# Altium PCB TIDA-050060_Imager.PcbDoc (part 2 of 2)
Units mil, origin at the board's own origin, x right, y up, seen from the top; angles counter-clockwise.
Board outline 989.05 x 988.04 mil, 6 copper layers (TOP, GND1, POWER1, INNER1, GND2, BOTTOM), stack 61.2 mil thick; 79 components, 47 nets, 342 pads, 154 vias.
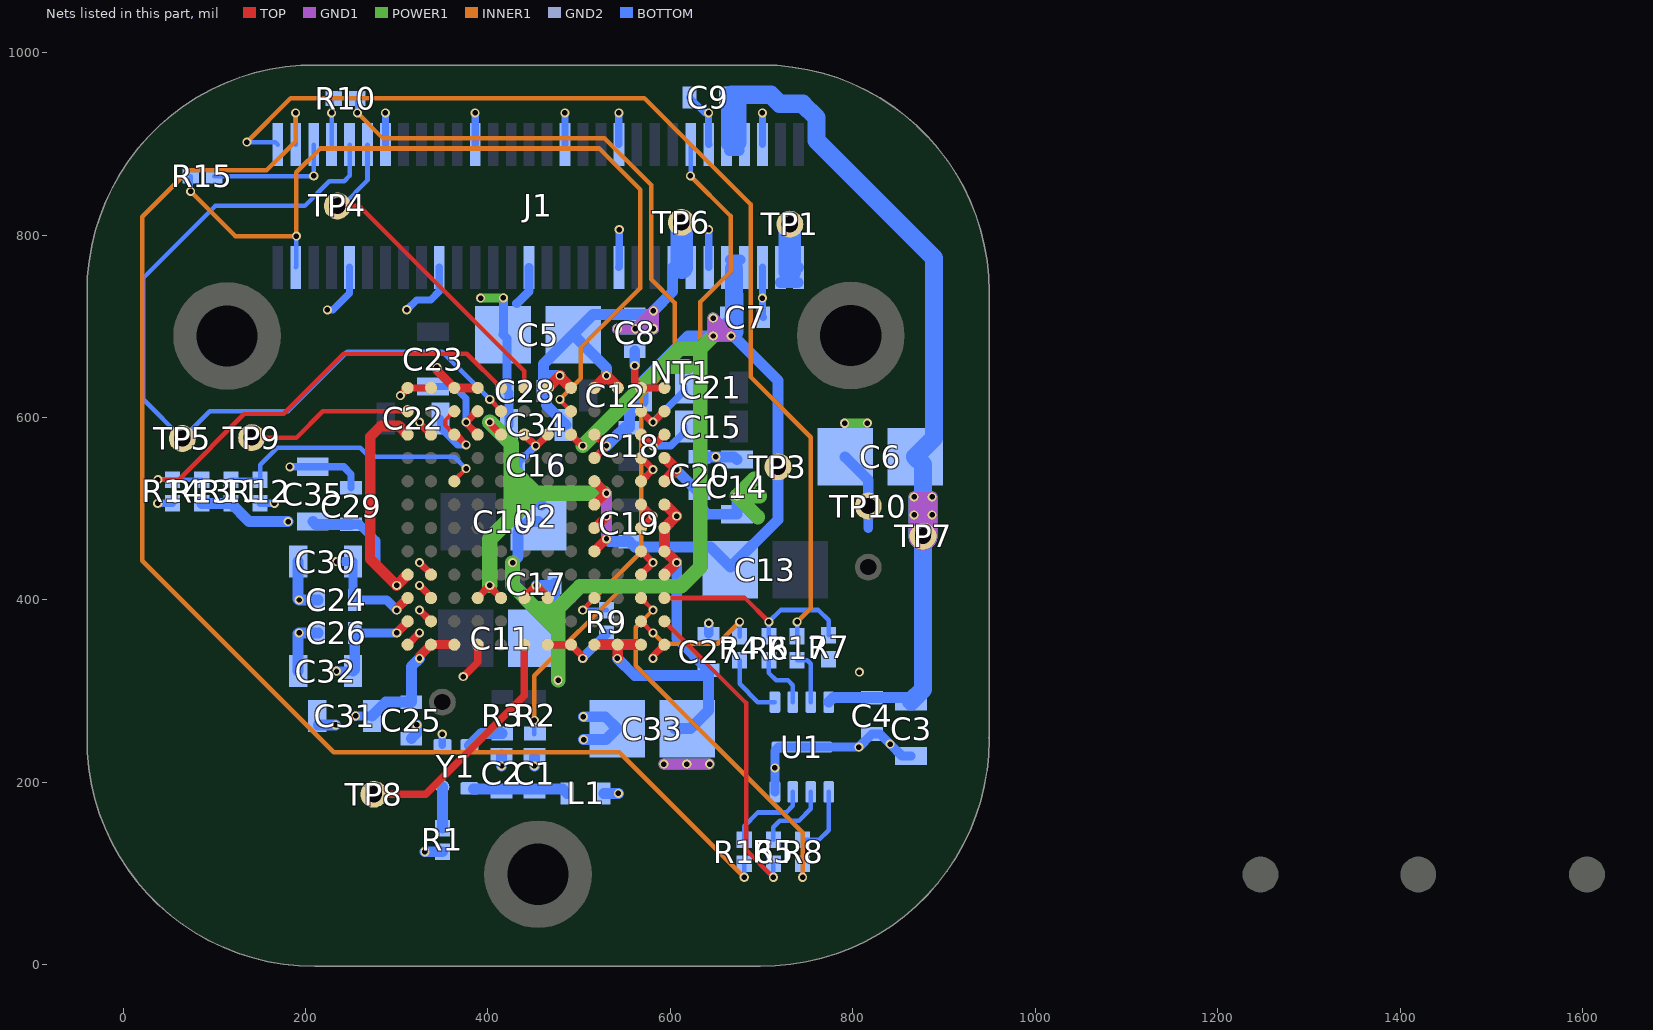
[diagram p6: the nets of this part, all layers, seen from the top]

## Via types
v1: diameter 10, hole 6, TOP to BOTTOM, tented both sides, 154 vias

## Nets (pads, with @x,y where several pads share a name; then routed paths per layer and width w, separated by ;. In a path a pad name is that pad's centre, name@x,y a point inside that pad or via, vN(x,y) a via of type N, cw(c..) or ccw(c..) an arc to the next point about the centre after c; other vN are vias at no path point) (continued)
DGND: C1.2 C2.2 C3.2 C4.2 C5.2 C6.2 C7.2 C8.2 C9.2 C14.2 C20.2 C24.2 C25.2 C26.2 C27.2 C28.2 C29.2 C30.2 C31.2 C32.2 C33.2 C34.2 C35.2 J1.5 J1.6 J1.11 J1.12 J1.21 J1.22 J1.27 J1.32 J1.37 J1.42 J1.47 J1.52 NT1.1 R7.1 R9.1 R12.1 R14.1 TP10.1 U1.4 U1.9 U2.A1 U2.A2 U2.A11 U2.A12 U2.C2 U2.D11 U2.E11 U2.F11 U2.G11 U2.H11 U2.J2 U2.J11 U2.K2 U2.L2 U2.M1 U2.M4 U2.M7 U2.M8 U2.M12 Y1.2 | length 1950.7
  TOP w8: v1(304,624) 312.01,632.01 U2.A1@312.01,632.51 U2.A2@337.6,632.51 ; U2.M1@312.01,351.02 v1(325,364) ; v1(325,389) 337.39,376.61 U2.L2@337.6,376.61 ; v1(325,416) 337.6,403.4 U2.K2@337.6,402.2 ; v1(325,441) 337.6,428.4 U2.J2@337.6,427.79 ; v1(325,595) 325,593.93 U2.C2@337.6,581.33 ; v1(373,316) 388.78,331.78 U2.M4@388.78,351.02 ; U2.M7@465.55,351.02 U2.M8@491.14,351.02 504,338.16 v1(504,336) ; v1(561,657) 561,639.42 U2.A11@567.91,632.51 U2.A12@593.5,632.51 ; U2.J11@567.91,427.79 567.91,427.91 v1(581,441) 568.62,453.38 U2.H11@567.91,453.38 ; U2.G11@567.91,478.97 580.95,492 v1(581,492) 568.44,504.56 U2.F11@567.91,504.56 ; U2.E11@567.91,530.15 568.15,530.15 v1(581,543) 568.26,555.74 U2.D11@567.91,555.74 ; v1(581,336) 581,338.51 U2.M12@593.5,351.02
  POWER1 w10: v1(392,731) v1@416.71,731 ; v1(791,593.71) v1@815.71,593.71
  INNER1 w10: v1@416.71,731 v1(417,731.29)
  BOTTOM w8: v1(38,506) R14.1@54.25,506 ; R12.1@150.25,506.02 v1(166,506) ; v1(183,546) C35.2@208,546 242,546 250,538 C29.2@250,523 ; v1(224,718) 230,718 248.31,736.31 J1.52@248.31,764.68 ; v1(287.61,934) 287.68,933.94 J1.47@287.68,899.32 ; v1(311,718.14) 321.86,729 337.18,729 346.73,738.56 J1.42@346.73,764.68 ; v1(350,253) 350,240.86 Y1.2@350.24,240.62 ; v1(386.04,934) 386.1,933.94 J1.37@386.1,899.32 ; v1(484.46,934) 484.53,933.94 J1.27@484.53,899.32 ; v1(543.52,934) 543.58,933.94 J1.21@543.58,899.32 ; J1.22@543.58,764.68 544,765.09 v1(544,806) ; C9.2@621,951 638,934 v1(641.94,934) 641.94,899.39 J1.11@642.01,899.32 ; J1.12@642.01,764.68 v1(642,806) ; v1(701,934) 701.06,933.94 J1.5@701.06,899.32 ; J1.6@701.06,764.68 701,764.61 v1(701,731) 701,711 C7.2@702,710
  BOTTOM w10: v1(417,731.29) 417,691.39 C5.2@416.61,691 421,686.61 C28.2@421,629 423,627 C34.2@423,592 ; 431.6,725 445.16,738.56 J1.32@445.16,764.68 ; v1(504,336) 504,337.01 R9.1@530,363.01 ; C27.2@642,363 642.06,363.06 v1(642.06,374.57) ; U1.4@714.63,189.57 v1(714.63,216) 714.63,234.63 718.79,238.79 U1.9@744.16,238.79 v1(806.79,238.79) C4.2@821,253 830,253 v1(841,242) 854,229 C3.2@864,229 ; 817,478.66 TP10.1@817,503
  BOTTOM w12: C32.2@192,322 192,363 v1(193,364) C26.2@214,364 ; C30.2@192,442 192,401 v1(193,400) C24.2@214,400 ; C31.2@214,263 v1(233,263) ; C25.2@316,248 322,254 v1(322,263) ; v1(415,218) C2.2@415,230 ; v1(451,218) C1.2@451,228.5 ; v1(504.71,272) 528.61,272 C33.2@541.61,259 529.61,247 v1(505,247) ; v1(561,657) C8.2@561,673 ; C20.2@632,557 670,557 C14.2@673,554 ; C6.2@791.61,557 817,531.61 TP10.1@817,503
  other v1: 807.22,321 650,557 816,594
EXT_CLK: J1.13 R2.1 | length 790.1
  INNER1 w5: v1(451,268) 451,317 551,417 613,417 633,437 633,727 666,760 666,821 v1(622,865)
  BOTTOM w5: R2.1@451,253 v1(451,268) ; v1(622,865) 622.32,865.32 J1.13@622.32,899.32
GPIO0: J1.53 R10.2 | length 51.7
  BOTTOM w5: J1.53@228.62,899.32 228.62,933.94 v1(228.56,934) 228.56,947.55 R10.2@231.01,950
GPIO1: J1.55 R15.1 | length 143.4
  BOTTOM w5: R15.1@99.99,864.7 208.58,864.7 208.94,865.06 J1.55@208.94,899.32
  other v1: 209,865
GPIO2: J1.57 R16.1 | length 1464.1
  INNER1 w5: v1(189.19,934) 189.19,902.94 157.25,871 72,871 21,820 21,443 231,233 544,233 v1(681,96)
  BOTTOM w5: v1(189.19,934) 189.25,933.94 J1.57@189.25,899.32 ; v1(681,96) R16.1@681,111.02
GPIO3: J1.59 R17.1 | length 1162.8
  INNER1 w5: v1(135.72,902) 184.03,950.31 571.34,950.31 688,833.65 688,644.5 754,578.5 754,391 v1(739,376)
  BOTTOM w5: v1(135.72,902) 166.89,902 J1.59@169.57,899.32 ; R17.1@739,360 v1(739,376)
HOLD: R17.2 U1.7 | length 58.7
  BOTTOM w5: R17.2@739,334.02 749.98,334.02 754,330 U1.7@754,288
I2C_SCL: J1.49 TP4.1 U2.A6 | length 394.4
  TOP w5: TP4.1@229,832 TP4.1@235,832 259,832 439.96,651.04 U2.A6@439.96,632.51
  BOTTOM w5: TP4.1@229,832 TP4.1@235,832 240,832 267.99,859.99 J1.49@267.99,899.32
I2C_SDA: J1.51 TP5.1 U2.B5 | length 916.9
  TOP w5: v1(402,620) 414.37,607.63 U2.B5@414.37,606.92
  BOTTOM w5: J1.51@248.31,899.32 248.31,865.01 242.3,859 226,859 199,832 101,832 22,753 22,620 TP5.1@65,577 95,607 180.87,607 245.87,672 350,672 v1(402,620)
NetC1_1: C1.1 C2.1 L1.2 Y1.4 | length 104.9
  BOTTOM w12: Y1.4@384.14,193 415,193 451,193 482,193 L1.2@487,188
NetC15_1: C15.1 U2.C11 U2.C12 | length 82.4
  TOP w5: v1@580.24,569 v1(581,569) v1@581.17,569
  TOP w8: U2.C11@567.91,581.33 v1@580.24,569 ; v1@581.17,569 U2.C12@593.5,581.33
  BOTTOM w8: v1(581,569) 600.61,569 615,583.39 C15.1@615,590
NetC21_1: C21.1 U2.B11 U2.B12 | length 87.5
  TOP w5: v1@579.83,595 v1(581,595) v1@581.58,595
  TOP w8: U2.B11@567.91,606.92 v1@579.83,595 ; v1@581.58,595 U2.B12@593.5,606.92
  BOTTOM w8: v1(581,595) 615,629 C21.1@615,633
NetC22_1: C22.1 U2.B3 U2.C3 | length 97.4
  TOP w5: U2.C3@363.19,581.33 353,591.52 353,596.73 U2.B3@363.19,606.92
  TOP w8: U2.C3@363.19,581.33 364.67,581.33 v1(376,570)
  BOTTOM w8: C22.1@348,599 348,589 367,570 v1(376,570)
NetC23_1: C23.1 U2.B4 U2.C4 | length 104.1
  TOP w8: U2.C4@388.78,581.33 376,594.11 v1(376,595) 387.92,606.92 U2.B4@388.78,606.92
  BOTTOM w8: C23.1@340,634 363,634 376,621 v1(376,595)
NetR1_1: R1.1 Y1.1 | length 45.1
  BOTTOM w12: R1.1@350,149.99 350.24,150.23 Y1.1@350.24,194.95
NetR3_1: R3.1 Y1.3 | length 41.3
  BOTTOM w12: Y1.3@379.76,240.62 392.78,253.64 R3.1@415.71,253.64
NetR4_2: R4.2 U2.L11 | length 144.9
  TOP w5: U2.L11@567.91,376.61 581,363.52 v1(581,364)
  INNER1 w5: v1(581,364) 593,352 652,352 v1(676,376)
  BOTTOM w5: R4.2@676,360 v1(676,376)
NetR5_2: R5.2 U2.L12 | length 345.1
  TOP w5: U2.L12@593.5,376.61 683,287.11 683,126 v1(713,96)
  BOTTOM w5: v1(713,96) R5.2@713,111.02
NetR6_2: R6.2 R7.2 U2.K12 | length 233.4
  TOP w5: U2.K12@593.5,402.2 681.8,402.2 v1(708,376)
  BOTTOM w5: R6.2@708,360 v1(708,376) 721,389 762.27,389 773.5,377.76 R7.2@773.5,361.23
NetR8_1: R8.1 U2.K11 | length 410.3
  TOP w5: U2.K11@567.91,402.2 567.91,402.09 v1(581,389)
  INNER1 w5: v1(581,389) 562,370 562,328 745,145 v1(745,96)
  BOTTOM w5: v1(745,96) R8.1@745,111.02
NetR9_2: R9.2 R10.1 U2.K9 | length 933.8
  TOP w5: v1(504,389) 504,389.46 U2.K9@516.73,402.2
  INNER1 w5: v1(257,934) 285,906 528,906 579,855 579,751.66 605,725.66 605,660.5 568,623.5 568,453 v1(504,389)
  BOTTOM w5: v1(257,934) R10.1@256.99,950 ; v1(504,389) R9.2@530,388.99
NetTP8_1: TP8.1 U2.M6 | length 265.7
  TOP w8: TP8.1@275,187 332,187 439.96,294.96 U2.M6@439.96,351.02
NetTP9_1: TP9.1 U2.B1 | length 183
  TOP w5: TP9.1@141,578 190.08,578 219,606.92 U2.B1@312.01,606.92
SCK: R6.1 U1.6 | length 64.5
  BOTTOM w5: R6.1@708,334.02 708,320 716,312 729,312 734.32,306.68 U1.6@734.32,288
SDI: R4.1 U1.5 | length 72.9
  BOTTOM w5: R4.1@676,334.02 676,308 696,288 U1.5@714.63,288
SDO: R5.1 U1.2 | length 81.9
  BOTTOM w5: R5.1@713,137 713,151 720,158 741,158 754,171 U1.2@754,189.57
SEL0: R11.1 R12.2 U2.E3 | length 310.5
  TOP w5: U2.E3@363.19,530.15 363.19,531.19 v1(376,544)
  BOTTOM w5: R11.1@118.25,532 R12.2@150.25,532 150.25,548.25 169,567 260,567 270.04,556.96 363.04,556.96 v1(376,544)
SEL1: R13.1 R14.2 U2.A5 | length 496.8
  TOP w5: v1(38.25,532) 61,532 133,604 176,604 242,670 376.88,670 U2.A5@414.37,632.51
  BOTTOM w5: v1(38.25,532) 54.24,532 R13.1@86.25,531.98
VAA_3V3: C7.1 C10.1 C11.1 C12.1 C13.1 C16.1 C17.1 C18.1 C19.1 J1.8 J1.10 TP3.1 U2.C5 U2.C6 U2.C7 U2.C8 U2.C9 U2.D9 U2.E9 U2.F9 U2.G9 U2.H9 U2.K4 U2.K5 U2.K6 U2.K7 | length 2744.4
  TOP w8: U2.K4@388.78,402.2 388.78,402.78 v1(402,416) 402,414.57 U2.K5@414.37,402.2 ; v1(402,595) 402,593.7 U2.C5@414.37,581.33 ; U2.K6@439.96,402.2 439.96,402.96 v1(453,416) 465.55,403.45 U2.K7@465.55,402.2 ; U2.C6@439.96,581.33 v1(452.29,569) 453.22,569 U2.C7@465.55,581.33 ; U2.C8@491.14,581.33 v1@503.47,569 ; U2.H9@516.73,453.38 U2.H9@516.73,453.73 ; U2.G9@516.73,478.97 U2.G9@516.97,478.97 ; U2.E9@516.73,530.15 U2.E9@516.85,530.15 ; U2.D9@516.73,555.74 v1(530,569) 517.67,581.33 U2.C9@516.73,581.33
  TOP w10: U2.H9@516.73,453.73 v1(530,467) ; U2.F9@516.73,504.56 529.17,517 v1(530,517) U2.E9@516.85,530.15 ; U2.G9@516.97,478.97 v1(530,492)
  GND1 w12: v1(530,467) v1(530,492) v1(530,517) ; v1(647,689.44) v1(666.69,689.44) v1(647,709.13) v1(647,689.44)
  POWER1 w16: v1(427,441) 427,416 452,391 ; 427,543 452,518 ; 433,517 452,517 ; 476,367 452,391 ; v1(477,312) 477,391 ; v1(504,569) 610.44,675.44 633,675.44 ; 593.73,656 618.73,656 ; v1(647,689.44) 633,675.44 ; 452,391 477,391 ; 477,391 501,415 612,415 633,436 633,675.44
  POWER1 w17: v1(402,416) 402,467 452,517 ; v1(402,595) 425.44,571.56 425.44,494 ; 458,517 v1@527,517
  GND2 w12: v1(530,467) v1(530,492) v1(530,517) ; v1(647,689.44) v1(666.69,689.44) v1(647,709.13) v1(647,689.44)
  BOTTOM w8: C16.1@433,548 433,549.71 v1(452.29,569)
  BOTTOM w10: C10.1@433,474 C16.1@433,548
  BOTTOM w12: v1(427,441) 433,447 433,474 445,486 C10.1@455.39,486 ; 434,529.36 C10.1@459,504.36 ; v1(453,416) 471,416 C17.1@473,418 473,380.61 477,376.61 v1(477,312) ; v1(530,467) 533,464 C19.1@555,464 561,458 644,458 666,436 718,488 TP3.1@718,546 718,640.45 v1@669.78,688.67 ; v1(530,569) 550,589 C18.1@555,589 555,602 570,617 C12.1@570,624 570,640 619.44,689.44 v1(647,689.44) C7.1@662,704.44 ; J1.10@666,773 J1.8@676.38,773 ; 669.78,763.46 671,764.68
  BOTTOM w20: 669.78,763.46 669.95,710.03 670,694
VDD_1V1: C5.1 C8.1 C14.1 C20.1 C24.1 C25.1 C26.1 C27.1 C28.1 C30.1 C31.1 C32.1 C33.1 C34.1 J1.14 J1.16 TP6.1 U2.A3 U2.A4 U2.A7 U2.A8 U2.A9 U2.A10 U2.D12 U2.E12 U2.F12 U2.G12 U2.H12 U2.J12 U2.K1 U2.L1 U2.M2 U2.M3 U2.M9 U2.M10 U2.M11 | length 1978.8
  TOP w5: U2.D12@593.5,555.74 U2.D12@594.26,555.74 ; v1@606.36,543 v1(607,543)
  TOP w8: v1(300,389) v1@300,390.19 ; U2.L1@312.01,376.01 U2.L1@312.01,376.61 ; U2.A7@465.55,632.51 U2.A7@466.49,632.51 ; v1@479,644.65 v1(479,646) ; U2.A8@491.14,632.14 U2.A8@491.14,632.51 ; v1(542,336) v1@542.32,336.32 ; U2.A10@542.32,632.51 U2.A10@542.32,633.46 ; U2.J12@593.5,427.79 U2.J12@593.79,427.79 ; U2.H12@593.5,453.38 U2.H12@594.62,453.38 ; U2.F12@593.5,504.56 U2.F12@594.44,504.56 ; v1@606.54,492 v1(607,492)
  TOP w10: v1(300,364) U2.L1@312.01,376.01 ; v1@300,390.19 U2.K1@312.01,402.2 ; v1(325,336) 325,338.42 U2.M2@337.6,351.02 U2.M3@363.19,351.02 ; v1(344,655) 344,651.7 U2.A3@363.19,632.51 U2.A4@388.78,632.51
  TOP w12: U2.A7@465.55,632.55 v1(479,646) ; v1@479,644.65 U2.A8@491.14,632.51 ; U2.M9@516.73,351.02 U2.M10@542.32,351.02 ; U2.A9@516.73,632.51 530,645.78 U2.A10@542.32,633.46 ; v1@542.32,336.32 U2.M10@542.32,351.02 ; U2.M11@567.91,351.02 U2.M10@542.32,351.02 ; U2.H12@593.5,453.38 U2.G12@593.5,478.97 v1@606.54,492 ; U2.E12@593.5,530.15 v1@606.36,543 ; U2.J12@593.79,427.79 v1(607,441) U2.H12@594.62,453.38 ; U2.D12@594.26,555.74 v1(607,543) ; U2.F12@594.44,504.56 v1(607,492)
  GND1 w12: v1(542,697.31) v1(561.69,697.31) ; v1(593,220) v1(618,220) v1@642.42,220 ; v1(561.69,697.31) v1(581.37,697.31) v1(581.37,717) v1(561.69,697.31)
  POWER1 w16: 692,533 v1(673,514) ; 696,491 v1(673,514) ; 698,514 v1(673,514)
  GND2 w12: v1(542,697.31) v1(561.69,697.31) ; v1(593,220) v1(618,220) v1@642.42,220 ; v1(561.69,697.31) v1(581.37,697.31) v1(581.37,717) v1(561.69,697.31)
  BOTTOM w10: v1(234,322) C32.1@252,322 ; v1(234,442) C30.1@252,442 252,402 C24.1@254,400 289,400 v1(300,389) ; C26.1@254,364 v1(300,364) ; v1(255,273) C31.1@273,273
  BOTTOM w12: C32.1@252,322 254,324 C26.1@254,364 ; C31.1@273,273 288,288 C25.1@316,288 316,327 v1(325,336) ; v1(479,646) 461,646 ; C34.1@483,592 485.79,592 464,613.79 464,626 C28.1@461,629 461,646 ; v1(530,646) 530,654.39 C5.1@493.39,691 ; v1(542,336) 561,317 636,317 C27.1@642,323 ; C33.1@604.61,259 C33.1@618.39,259 622,259 642,279 C27.1@642,323 ; v1(607,441) 607,358 C27.1@642,323 ; v1(607,543) 607,542 C20.1@632,517 632,503 641,494 C14.1@673,494 v1(673,514) ; 612.48,764.68 J1.16@602.64,764.68 602.64,738.27 v1(581.37,717) 577.37,713 C8.1@561,713 515.39,713 C5.1@493.39,691 ; TP6.1@612.48,812.48 TP6.1@614,814 ; 461,646 461,658.61 C5.1@493.39,691
  BOTTOM w25: 612.48,764.68 TP6.1@612.48,812.48
  other v1: 643,220
VDD_1V8: C3.1 C4.1 C6.1 C9.1 C29.1 C35.1 J1.7 J1.9 L1.1 R1.2 R11.2 R13.2 TP7.1 U1.8 U2.C1 U2.J1 | length 1776.4
  TOP w8: U2.J1@311.79,427.79 U2.J1@312.01,427.79
  TOP w12: U2.J1@311.79,427.79 v1(300,416) 271,445 271,579 283,591 302.34,591 U2.C1@312.01,581.33
  GND1 w12: v1(867.31,513) v1(887,513) v1(887,493.31) ; v1(867.31,513) v1(867.31,493.31) v1(887,493.31) ; v1(867.31,513) v1(887,493.31)
  GND1 w32: TP7.1@877,470 877,492
  GND2 w12: v1(867.31,493.31) v1(867.31,513) v1(887,513) v1(887,493.31)
  GND2 w32: TP7.1@877,470 877,492
  BOTTOM w10: C29.1@250,483 259,483 277,465 277,439 v1(300,416)
  BOTTOM w12: R13.2@86.25,506 118.24,506 138.27,486 v1(181,486) ; C35.1@208,486 211,483 C29.1@250,483 ; v1(331,124) R1.2@350,124.01 ; L1.1@527,188 v1(543,188) ; J1.9@661.69,899.32 661.69,950.31 C9.1@661,951 689.31,951 692,953.69 ; J1.9@665,893 675.38,893 ; U1.8@773.69,288 778.69,293 C4.1@821,293 860,293 C3.1@864,289
  BOTTOM w20: C9.1@667,954 710,954 720,944 745.08,944 760.34,928.74 760.34,903.66 889,775 889,577.61 C6.1@868.39,557 877,548.39 877,513 TP7.1@877,470 877,302 C3.1@864,289
  BOTTOM w25: 671,902 671,949.8
VDD_3V8: J1.2 J1.4 TP1.1 | length 85.8
  BOTTOM w12: J1.4@721,748 J1.2@739.87,748 ; 731,774.11 730.18,774.11 739.61,764.68 J1.2@740.43,764.68
  BOTTOM w25: 731,760 TP1.1@731,812
WP: R16.2 U1.3 | length 92.8
  BOTTOM w5: R16.2@681,137 681,152 696,167 727,167 734.32,174.32 U1.3@734.32,189.57
XCE: R8.2 U1.1 | length 75
  BOTTOM w5: R8.2@745,137 763,137 773.69,147.69 U1.1@773.69,189.57
XERR: J1.58 R15.2 U2.B8 | length 948.6
  TOP w5: v1(479,620) 479,619.06 U2.B8@491.14,606.92
  INNER1 w5: v1(74,848) 123,799 v1(190,799) 190,869 216,895 522,895 567,850 567,742 502,677 502,643 v1(479,620)
  BOTTOM w5: v1(74,848) R15.2@74.01,864.7 ; J1.58@189.25,764.68 190,765.43 v1(190,799)
pads on no net: FID1.1 FID2.1 FID3.1 J1.1 J1.3 J1.15 J1.17 J1.18 J1.19 J1.20 J1.24 J1.26 J1.28 J1.30 J1.34 J1.36 J1.38 J1.40 J1.44 J1.46 J1.48 J1.50 J1.54 J1.56 J1.60 MH2.1 MH3.1 MH4.1 U2.B2 U2.B9 U2.B10 U2.D3

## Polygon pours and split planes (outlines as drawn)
AGND on GND1 "GND1_AGND_P004" (solid, remove dead copper, pour order 4): 541,410 823,410 834,421 834,454 822,466 792.36,466 779,479.36 779,529.5 662.5,646 571.71,646 571.71,644.71 548,621 548,432 541,425
AGND on GND1 "GND1_AGND_P008" (solid, remove dead copper, pour order 8): 423,645 393,675 321,675 289,643 262,643 255,650 255,681 267,693 305,693 326,714 332,720 407,720 452,675 452,608 464,596 449,581 423,581
AGND on GND1 "GND1_AGND_P012" (solid, remove dead copper, pour order 12): 539.68,613.97 571.71,646 661,646 665,642 665,595 658,588 624,588 602,610 574.44,610 561,596.56 539.86,596.56
AGND on GND1 "GND1_AGND_P010" (solid, remove dead copper, pour order 10): 396,530.35 353,487.35 353,410 376,387 465,387 488,410 541,410 561,430 561,616 552,625 518,625 508.29,615.29 493,600 447,600 422,575 400,575 396,571
DGND on GND1 "GND1-DGND" (solid, pour order 16): 211.53,963.54 698.93,963.54 718.7,962.68 738.31,960.1 757.63,955.81 776.5,949.87 794.78,942.29 812.33,933.16 829.01,922.53 844.71,910.48 859.3,897.12 872.66,882.53 884.71,866.83 895.34,850.15 904.47,832.6 912.04,814.32 917.99,795.45 922.28,776.13 924.86,756.52 925.72,736.75 925.72,249.35 924.86,229.59 922.28,209.97 917.99,190.65 912.04,171.79 904.47,153.51 895.34,135.96 884.71,119.27 872.66,103.57 859.3,88.99 844.71,75.62 829.01,63.58 812.33,52.95 794.78,43.81 776.5,36.24 757.63,30.29 738.31,26.01 718.7,23.43 698.93,22.56 211.53,22.56 191.77,23.43 172.15,26.01 152.83,30.29 133.96,36.24 115.69,43.81 98.14,52.95 81.45,63.58 65.75,75.62 51.17,88.99 37.8,103.57 25.76,119.27 15.13,135.96 5.99,153.51 -1.58,171.79 -7.53,190.65 -11.81,209.97 -14.4,229.59 -15.26,249.35 -15.26,736.75 -14.4,756.52 -11.81,776.13 -7.53,795.45 -1.58,814.32 5.99,832.6 15.13,850.15 25.76,866.83 37.8,882.53 51.17,897.12 65.75,910.48 81.45,922.53 98.14,933.16 115.69,942.29 133.96,949.87 152.83,955.81 172.15,960.1 191.77,962.68 211.53,963.54
DGND on GND2 "GND1-DGND" (solid, pour order 22): 211.53,963.54 698.93,963.54 718.7,962.68 738.31,960.1 757.63,955.81 776.5,949.87 794.78,942.29 812.33,933.16 829.01,922.53 844.71,910.48 859.3,897.12 872.66,882.53 884.71,866.83 895.34,850.15 904.47,832.6 912.04,814.32 917.99,795.45 922.28,776.13 924.86,756.52 925.72,736.75 925.72,249.35 924.86,229.59 922.28,209.97 917.99,190.65 912.04,171.79 904.47,153.51 895.34,135.96 884.71,119.27 872.66,103.57 859.3,88.99 844.71,75.62 829.01,63.58 812.33,52.95 794.78,43.81 776.5,36.24 757.63,30.29 738.31,26.01 718.7,23.43 698.93,22.56 211.53,22.56 191.77,23.43 172.15,26.01 152.83,30.29 133.96,36.24 115.69,43.81 98.14,52.95 81.45,63.58 65.75,75.62 51.17,88.99 37.8,103.57 25.76,119.27 15.13,135.96 5.99,153.51 -1.58,171.79 -7.53,190.65 -11.81,209.97 -14.4,229.59 -15.26,249.35 -15.26,736.75 -14.4,756.52 -11.81,776.13 -7.53,795.45 -1.58,814.32 5.99,832.6 15.13,850.15 25.76,866.83 37.8,882.53 51.17,897.12 65.75,910.48 81.45,922.53 98.14,933.16 115.69,942.29 133.96,949.87 152.83,955.81 172.15,960.1 191.77,962.68 211.53,963.54
VDD_1V8 on BOTTOM "GND1-DGND" (solid, pour order 30): 838.25,785.58 754.34,869.49 754.34,918.66 753.75,920.08 746.42,927.41 745,928 699,928 698.93,963.54 718.7,962.68 738.31,960.1 757.63,955.81 776.5,949.87 794.78,942.29 812.33,933.16 829.01,922.53 844.71,910.48 859.3,897.12 872.66,882.53 884.71,866.83 895.34,850.15 904.47,832.6 912.04,814.32 917.99,795.45 922.28,776.13 924.86,756.52 924.86,296 837.59,296
DGND on BOTTOM "BOTTOM_DGND_P032" (solid, remove dead copper, pour order 32): 882,543 801.01,623.99 746,679 746,734.99 180,734.99 180,269 239,210 871,210 882,221
VDD_1V8 on POWER1 "POWER1_VDD_1V8_P020" (solid, remove dead copper, pour order 20): 856,345 713,202 360,202 310,252 310,420 303,427 291,427 268,404 268,259 261.92,252.92 242.08,252.92 193,302 193,496.29 167.29,496.29 144,473 144,171 197,118 807,118 898.22,209.22 898.22,517.78 892,524 861,524 856,519
VDD_1V1 on POWER1 "POWER1_VDD_1V1_P024" (solid, remove dead copper, pour order 24): 282,749 203,670 203,302.32 204.68,302.32 245,262 259,262 265,268 265,620 288,643 451,643 477,669 564,669 629.99,734.99 659.01,734.99 685.29,708.71 685.29,366.29 567,248 567,216 574,209 679,209 792.36,322.36 792.36,516.08 897,620.72 897,751 861,787 320,787
DGND on POWER1 "GND1-DGND" (solid, remove dead copper, pour order 28): 211.53,963.54 698.93,963.54 718.7,962.68 738.31,960.1 757.63,955.81 776.5,949.87 794.78,942.29 812.33,933.16 829.01,922.53 844.71,910.48 859.3,897.12 872.66,882.53 884.71,866.83 895.34,850.15 904.47,832.6 912.04,814.32 917.99,795.45 922.28,776.13 924.86,756.52 925.72,736.75 925.72,249.35 924.86,229.59 922.28,209.97 917.99,190.65 912.04,171.79 904.47,153.51 895.34,135.96 884.71,119.27 872.66,103.57 859.3,88.99 844.71,75.62 829.01,63.58 812.33,52.95 794.78,43.81 776.5,36.24 757.63,30.29 738.31,26.01 718.7,23.43 698.93,22.56 211.53,22.56 191.77,23.43 172.15,26.01 152.83,30.29 133.96,36.24 115.69,43.81 98.14,52.95 81.45,63.58 65.75,75.62 51.17,88.99 37.8,103.57 25.76,119.27 15.13,135.96 5.99,153.51 -1.58,171.79 -7.53,190.65 -11.81,209.97 -14.4,229.59 -15.26,249.35 -15.26,736.75 -14.4,756.52 -11.81,776.13 -7.53,795.45 -1.58,814.32 5.99,832.6 15.13,850.15 25.76,866.83 37.8,882.53 51.17,897.12 65.75,910.48 81.45,922.53 98.14,933.16 115.69,942.29 133.96,949.87 152.83,955.81 172.15,960.1 191.77,962.68 211.53,963.54

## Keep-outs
Keep-Out Layer:
  text ".Layer_Name" at 577,-858.49 h60

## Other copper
TOP:
  text ".Layer_Name" at 577,-858.49 h60
GND1:
  region net AGND: 360,484 360,465 341,446 341,407 361,387 376,387 376,484
  region net AGND: 423.47,597 423.47,586 412.47,575 412.47,570 433.53,570 433.53,596.93 433.47,597
POWER1:
  pour cut-out: 685.29,709.14 685.29,634.86 690,639.57 690,704.43
  region net VDD_1V8: 856,519 856,462 867,451 887,451 898.22,462.22 898.22,517.78 892,524 861,524
  region net VAA_3V3: 417,494 417,470 491,470 532,511 532,522 531,522 528,525 455,525 455,523.56 425.44,494
  region net VDD_1V1: 525,691 586,691 592,697 592,717.49 585.49,724 555,724 525,694
  region net VAA_3V3: 634.09,635 672,671.96 672,691 649,714 638,714 600,676 600,662.35 627.35,635
BOTTOM:
  region net VDD_1V8: 908.36,279.5 925,296.14 925,328 854,328 826,300 826,291 837.5,279.5
  region net VDD_1V8: 687.02,876 656.02,876 656.02,924.02 696.02,964.02 696.02,944.02 687.02,935.02
  region net VAA_3V3: 656.06,788 687.06,788 687.06,731 647.06,691 647.06,725.05 656.06,734.05
  region net VDD_1V1: 597,788 628,788 628,731 588,691 588,732 597,741
  region net DGND: 386.39,660 386.39,732 390.39,736 447.71,736 448.39,735.33 448.39,660
  region net AGND: 712,403.11 714,401.11 822.11,401.11 832,411 832,454 821.89,464.11 712,464.11
  region net DGND: 832,488 832,593 820,605 778,605 758,585 758,488
  region net AGND: 344,518 344,441 344,438 347,435 389,435 409,455 409,518
  region net AGND: 344,327 344,418 348,422 380.14,422 406,396.14 406,327
  region net DGND: 572,288.39 570,290.39 499.71,290.39 495,285.68 495,233.31 500.92,227.39 572,227.39
  region net VDD_1V1: 588,290 586,288 586,217.71 590.71,213 647,213 649,215 649,290
  region net VAA_3V3: 614,683 614,692 665,743 681,743 681,683
  region net VDD_1V1: 513,722.14 513.14,722 589,722 592,719 592,695 588,691 513,691
  text ".Layer_Name" at 577,-858.49 h60

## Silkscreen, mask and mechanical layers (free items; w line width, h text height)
Top Overlay:
  text ".Layer_Name" at 577,-858.49 h60
Bottom Overlay:
  text ".Layer_Name" at 577,-858.49 h60
Top Paste:
  text ".Layer_Name" at 577,-858.49 h60
Bottom Paste:
  text ".Layer_Name" at 577,-858.49 h60
Top Solder:
  text ".Layer_Name" at 577,-858.49 h60
  text ".Layer_Name" at 577,-858.49 h60
Bottom Solder:
  text ".Layer_Name" at 577,-858.49 h60
Drill Guide:
  text ".Layer_Name" at 577,-858.49 h60
M1 Board Outline:
  lines w3: -38.01,737 cw(c209,738) 212,984.99 700,985 cw(c701.01,738) 948,735 ; -38,738 -38,250 ccw(c208.99,247) 209.99,-0.01 698,0 ccw(c701,246.99) 948.01,247.99 ; 948,250 948,737
  text ".Layer_Name" at 577,-858.49 h60
M2 Board Dimensions:
  rectangle: 0,-275 125,-150
  rectangle: 125,-400 500,-275
  lines w1: -148.7,3.3 385.95,3.3 ; -148.7,983.7 370.93,983.7 ; -138.2,465.8 -138.2,0.8 ; -138.2,485.8 -138.2,981.2 ; -133.7,471.8 -127.7,471.8 ; -133.7,475.8 -127.7,475.8 ; -130.7,472.8 -130.7,478.8 ; -35.7,591.46 -35.7,1066.3 ; 944.7,610.78 944.7,1066.3 ; -138.2,0.8 -136.2,13.8 -140.2,13.8 -138.2,0.8 ; -138.2,981.2 -140.2,968.2 -136.2,968.2 -138.2,981.2
  lines w3: -16,492 219,492 689,492 924,492 ; 285,393.48 796.9,689.44 ; 455,23 455,258 455,728 455,963 ; 625.08,393.07 114.1,689.44 ; 114.1,689.44 796.9,689.44 ; 114.1,689.44 455,99 796.9,689.44
  lines w7: 0,-275 1000,-275 ; 125,-400 125,-150 ; 250,-400 250,-150 ; 500,-400 500,-150 ; 750,-400 750,-150 ; 0,-400 1000,-400 1000,-150 0,-150 0,-400
  text "980" at -159.7,471.8 h8
  text "5" at -122.7,471.8 h8
  text ".Layer_Name" at 577,-858.49 h60
M3 3D STEP Top:
  text ".Layer_Name" at 577,-858.49 h60
M4 3D STEP Bottom:
  text ".Layer_Name" at 577,-858.49 h60
M5 Assembly Top:
  lines w10: -292,-930.17 6308,-930.17 ; -292,-726.83 6310,-726.83 ; -292,-523.5 -292,-1133.5 3713,-1133.5 6310,-1133.5 6310,-523.5 -291.5,-523.5 -291.5,-1133.5 1284,-1133.5 ; 2173,-1133.5 2173,-523.5 ; 3440,-726.83 3440,-523.5 ; 4280,-726.83 4280,-523.5 ; 4902,-1140 4902,-937.17
  text "COMPONENTS MARKED 'DNP' SHOULD NOT BE POPULATED." at 1153.5,-318.5 h60
  text "ASSEMBLY VARIANT:" at 1153,-434 h60
  text ".VariantName" at 2189,-434 h60
  text "PCB VIEWED FROM TOP SIDE" at -228.5,-655.67 h60
  text "BOARD #:" at 2248,-655.67 h60
  text ".PRJ_Number" at 2793.5,-655.67 h60
  text "REV:" at 3638,-655.67 h60
  text ".PCB_Rev" at 3929.5,-655.67 h60
  text "SVN REV:" at 4476,-655.67 h60
  text ".VersionControl_RevNumber" at 4982,-655.67 h60
  text "TID #:" at 2248,-859 h60
  text ".TID" at 2793.5,-859 h60
  text "PLOT NAME =" at -228.5,-1064.34 h60
  text ".plot_File_Name" at 577,-1064.34 h60
  text "GENERATED    :" at 2250,-1064.34 h60
  text ".Print_Date" at 3119.5,-1064.34 h60
  text ".Print_Time" at 3848.5,-1064.34 h60
  text "TEXAS INSTRUMENTS" at 5113,-1064.34 h60
M6 Assembly Bottom:
  lines w10: -292.5,-727.33 6309.5,-727.33 ; -290.5,-930.67 6309.5,-930.67 ; 1115.5,-1140.5 1115.5,-937.67 ; 1737.5,-727.33 1737.5,-524 ; 2577.5,-727.33 2577.5,-524 ; 3844.5,-1134 3844.5,-524 ; 4733.5,-1134 6309,-1134 6309,-524 -292.5,-524 -292.5,-1134 2304.5,-1134 6309.5,-1134 6309.5,-524
  text "COMPONENTS MARKED 'DNP' SHOULD NOT BE POPULATED." at 6102,-318 h60
  text ".VariantName" at 5058,-434 h60
  text "ASSEMBLY VARIANT:" at 6097,-434 h60
  text ".VersionControl_RevNumber" at 1035.5,-656.17 h60
  text "SVN REV:" at 1541.5,-656.17 h60
  text ".PCB_Rev" at 2088,-656.17 h60
  text "REV:" at 2379.5,-656.17 h60
  text ".PRJ_Number" at 3224,-656.17 h60
  text "BOARD #:" at 3769.5,-656.17 h60
  text "PCB VIEWED FROM BOTTOM SIDE" at 6246,-656.17 h60
  text ".TID" at 3224,-859.5 h60
  text "TID #:" at 3769.5,-859.5 h60
  text "TEXAS INSTRUMENTS" at 904.5,-1064.84 h60
  text ".Print_Time" at 2169,-1064.84 h60
  text ".Print_Date" at 2898,-1064.84 h60
  text "GENERATED    :" at 3767.5,-1064.84 h60
  text ".plot_File_Name" at 5440.5,-1064.84 h60
  text "PLOT NAME =" at 6246,-1064.84 h60
M9 Title Sheet:
  drawing of 57 lines, arcs and shapes, not listed
  text "1" at 739.84,8036.5 h70
  text "2" at 3235.5,8036.5 h70
  text "3" at 5724.84,8036.5 h70
  text "4" at 8231.51,8036.5 h70
  text "5" at 10730.5,8036.5 h70
  text "6" at 13235.5,8036.5 h70
  text "A" at -416.5,6893.5 h70
  text "A" at 14383.5,6893.5 h70
  text "B" at -416.5,4513.5 h70
  text "B" at 14383.5,4513.5 h70
  text "C" at -416.5,2138.5 h70
  text "C" at 14383.5,2138.5 h70
  text "PROJECT TITLE:" at 11343.5,277.5 h45
  text ".PRJ_Title" at 11393.5,144.17 h70
  text "DESIGNED FOR:" at 11343.5,-23.5 h45
  text ".PRJ_Customer" at 11393.5,-163.5 h70
  text "D" at -416.5,-231.5 h70
  text "D" at 14383.5,-231.5 h70
  text "FILE NAME:" at 11343.5,-323.5 h45
  text ".PCB_File_Name_No_Path" at 11393.5,-443.5 h70
  text "Texas Instruments (TI) and/or its licensors do not warrant the accuracy or completeness of this specification" at 6374,-605.34 h45
  text "ENGINEER:" at 11343.5,-613.5 h45
  text "LAYOUT BY:" at 12848.5,-613.5 h45
  text "or any information contained therein. TI and/or its licensors do not warrant that this design will meet" at 6329.01,-718 h45
  text ".PRJ_Engineer" at 11393.5,-768.49 h70
  text ".PCB_Layout" at 12899,-768.49 h70
  text "the specifications, will be suitable for your application or fit for any particular purpose, or will operate in" at 6329.01,-830.67 h45
  text ".Layer_Name" at 577,-858.49 h60
  text "ALTIUM DESIGNER VERSION:" at 12848.5,-923.5 h45
  text "an implementation. TI and/or its licensors do not warrant that the design is production worthy. You should" at 6329.01,-943.33 h45
  text "completely validate and test your design implementation to confirm the system functionality for your application." at 6374,-1056 h45
  text ".print_Scale" at 11393.5,-1056.83 h70
  text ".Application_BuildNumber" at 12899,-1056.83 h70
  text "1" at 739.84,-1263.5 h70
  text "2" at 3235.5,-1263.5 h70
  text "3" at 5724.84,-1263.5 h70
  text "4" at 8231.51,-1263.5 h70
  text "5" at 10730.5,-1263.5 h70
  text "6" at 13235.5,-1263.5 h70
M10 Fab Notes:
  drawing of 189 lines, arcs and shapes, not listed
  text "DESIGN INFORMATION" at 12382.02,6356.17 h60
  text "MIN. TRACK WIDTH:" at 11737.46,6224.05 h60
  text "8" at 12833.7,6224.05 h60
  text "MIL" at 12988.46,6224.05 h60
  text "MIN. CLEARANCE:" at 11737.46,6099.92 h60
  text "0.2" at 12773.7,6099.93 h60
  text "mm" at 12988.46,6099.92 h60
  text "MIN. VIA PAD SIZE:" at 11737.46,5975.8 h60
  text "24" at 12803.71,5975.8 h60
  text "MIL" at 12988.46,5975.8 h60
  text "0.05mm (2MIL)" at 12432.46,5845.9 h60
  text "MINIMUM ANNULAR RING" at 11408.23,5837.67 h60
  text "EXTERNAL" at 13140.46,5837.67 h60
  text "PER" at 11608.23,5727.55 h60
  text "IPC-D-275 CLASS 2 LEVEL C" at 11828.23,5727.54 h60
  text "MIL, HOLES" at 13316.46,5627.07 h60
  text "+/-" at 12924,5618.48 h60
  text "+/-" at 13778,5618.48 h60
  text "REGISTRATION TOLERANCES:" at 11408.23,5617.42 h60
  text "METAL" at 12608,5617.42 h60
  text "5" at 13184.2,5617.42 h60
  text "3" at 14017.2,5617.42 h60
  text "MIL" at 14133.46,5617.42 h60
  text "HOLE SIZE TOLERANCE (UNLESS OTHERWISE SPECIFIED):" at 11408.23,5519.1 h60
  text "+/-" at 13778,5516.23 h60
  text "3" at 14017.2,5515.17 h60
  text "MIL" at 14133.46,5515.17 h60
  text "MATERIAL:" at 11333.46,5377.52 h60
  text "FR-4 High Tg" at 12319.9,5249 h60
  text "X" at 12175.46,5241.01 h60
  text "FR-408" at 11754.46,5236.49 h60
  text "OTHER" at 13242.46,5236.49 h60
  text "62 MIL (1.6mm) +/-10%" at 12074.56,5093.46 h60
  text "X" at 11954.46,5091.01 h60
  text "THICKNESS:" at 11408.23,5085.24 h60
  text "OTHER" at 13359.46,5085.24 h60
  text "TOLERANCE:" at 11408.23,4946.92 h60
  text "X" at 12256.46,4946.92 h60
  text "ANSI IPC-6012 TYPE 3 CLASS 2" at 12434.48,4946.92 h60
  text "OTHER +/-" at 12434.46,4802.73 h60
  text "BOW & TWIST:" at 11408.23,4657.54 h60
  text "X" at 12256.46,4657.54 h60
  text "ANSI IPC-6012 TYPE 3 CLASS 2" at 12434.48,4657.54 h60
  text "OTHER +/-" at 12434.46,4510.85 h60
  text "DRILLING:" at 11333.46,4380.23 h60
  text "NC_DRILL FILES" at 13094.46,4275.04 h60
  text "REFERENCE:" at 11408.23,4271.1 h60
  text "X" at 12065.46,4271.01 h60
  text "AS SHOWN" at 12243.46,4271.1 h60
  text "X" at 12966.46,4271.1 h60
  text "OTHER" at 13392.46,4128.85 h60
  text "PTH COPPER THICKNESS:" at 11407.91,4125.32 h60
  text "X" at 12547.14,4125.32 h60
  text "20-30 um" at 12675.14,4125.32 h60
  text "BOARD FINISH:" at 11333.46,3977.73 h60
  text "SILKSCREEN:" at 11488.68,3867.6 h60
  text "X" at 12446.46,3867.6 h60
  text "TOP" at 12563.46,3867.6 h60
  text "X" at 12956.46,3867.6 h60
  text "BOTTOM" at 13074.46,3867.6 h60
  text "SILKSCREEN COLOR:" at 11488.68,3712.41 h60
  text "X" at 12445.46,3712.41 h60
  text "WHITE" at 12563.46,3712.41 h60
  text "OTHER" at 13074.46,3712.41 h60
  text "X" at 12576.46,3568.96 h60
  text "GREEN" at 12694.46,3568.96 h60
  text "OTHER" at 13312.46,3568.96 h60
  text "SOLDER RESIST COLOR:" at 11488.68,3562.1 h60
  text "X" at 12576.46,3414.71 h60
  text "MATTE" at 12694.46,3414.71 h60
  text "SEMI-GLOSS" at 13312,3414.07 h60
  text "IMMERSION GOLD (ENIG)" at 12394.46,3241.94 h60
  text "ENEPIG" at 13732,3234.72 h60
  text "SURFACE FINISH:" at 11333.46,3233.72 h60
  text "X" at 12216.46,3233.72 h60
  text "IMM. TIN/SILVER OR EQUIV" at 11663,3096.4 h60
  text "OTHER" at 13094.46,3092.47 h60
  text "ARRAY/PANEL:" at 11333.46,2937.09 h60
  text "CUT AND TRIM PER M1 BOARD OUTLINE" at 12394.46,2928.87 h60
  text "N.C. ROUTE" at 12394.46,2792.9 h60
  text "X" at 13082.46,2792.9 h60
  text "V. SCORE" at 13260.46,2792.9 h60
  text "CERTIFICATION:" at 11333.46,2663.77 h60
  text "MATERIALS AND WORKMANSHIP FOR ALL PCBS" at 12058.46,2663.77 h60
  text "TO MEET OR EXCEED THE REQUIREMENTS OF:" at 12058.46,2569.71 h60
  text "X" at 11695.97,2441.08 h60
  text "ANSI IPC-A-600F CLASS ->" at 11823.96,2441.08 h60
  text "X" at 13471.97,2441.08 h60
  text "2" at 13581.96,2441.08 h60
  text "1" at 13266.96,2439.58 h60
  text "3" at 13935.96,2439.58 h60
  text "X" at 12507.97,2293.39 h60
  text "RoHS" at 12635.96,2293.39 h60
  text "OTHER" at 13280.36,2293.39 h60
  text "PER ORDER" at 13677.42,2293.39 h60
  text "ALL BOARDS MUST MEET OR EXCEED UL94-V0 REQUIREMENTS." at 11361,2139.57 h60
  text "PCB MUST BEAR THE UL94V-0 UL REGISTERED MATERIAL ID NUMBER" at 11361,2023.5 h60
  text "ADDITIONAL REQUIREMENTS:" at 11333.46,1854.08 h60
  text "MICROSECTION:" at 11408.23,1746.95 h60
  text "YES" at 12313.96,1746.95 h60
  text "REQUIRED" at 13175.46,1602.62 h60
  text "BARE BOARD ELEC. TEST:" at 11408.23,1599.76 h60
  text "NONE" at 12713.96,1599.76 h60
  text "X" at 13057.46,1599.76 h60
  text "PER ORDER" at 13767.46,1599.76 h60
  text "XX MIL VIAS REQUIRE NON-CONDUCTIVE FILL AND PLANARIZE" at 11576.38,1394.82 h59
  text "XX MIL VIAS REQUIRE CONDUCTIVE FILL AND PLANARIZE" at 11584.38,1290.84 h60
  text "OUTER XX MIL TRACES REQUIRE 50 OHM SINGLE-ENDED IMPEDANCE" at 11583.39,1127.46 h58
  text "LAYER 2 & 3 (INNER LAYERS) XX MIL WIDE, XX MIL SPACE / TRACES REQUIRE 100 OHM DIFFERENTIAL IMPEDANCE" at 11575.39,891.74 h60
  text ".Layer_Name" at 577,-858.49 h60
M11 Gerber Information:
  lines w10: -292,-930.17 6308,-930.17 ; -292,-726.83 6310,-726.83 ; -292,-523.5 -292,-1133.5 3713,-1133.5 6310,-1133.5 6310,-523.5 -291.5,-523.5 -291.5,-1133.5 1284,-1133.5 ; 2173,-1133.5 2173,-523.5 ; 3440,-726.83 3440,-523.5 ; 4280,-726.83 4280,-523.5 ; 4902,-1140 4902,-937.17
  text "ALL ARTWORK VIEWED FROM TOP SIDE" at -228.5,-655.67 h60
  text "BOARD #:" at 2248,-655.67 h60
  text ".PRJ_Number" at 2793.5,-655.67 h60
  text "REV:" at 3638,-655.67 h60
  text ".PCB_Rev" at 3929.5,-655.67 h60
  text "SVN REV:" at 4476,-655.67 h60
  text ".VersionControl_RevNumber" at 4982,-655.67 h60
  text "LAYER NAME =" at -228.5,-858.49 h60
  text "TID #:" at 2248,-859 h60
  text ".TID" at 2793.5,-859 h60
  text "PLOT NAME =" at -228.5,-1064.34 h60
  text ".plot_File_Name" at 577,-1064.34 h60
  text "GENERATED    :" at 2250,-1064.34 h60
  text ".Print_Date" at 3119.5,-1064.34 h60
  text ".Print_Time" at 3848.5,-1064.34 h60
  text "TEXAS INSTRUMENTS" at 5113,-1064.34 h60
M12 Stackup:
  drawing of 399 lines, arcs and shapes, not listed
  text "Layer" at 6596.34,7283 h60
  text "Name" at 7006.26,7283 h60
  text "Material" at 7936,7283 h60
  text "Thickness" at 8795.77,7283 h60
  text "Constant" at 9445.6,7283 h60
  text "Board Layer Stack" at 10015.46,7283 h60
  text "Top Overlay" at 7006.26,7163 h60
  text "Top Solder" at 7006.26,7043 h60
  text "Solder Resist" at 7936,7043 h60
  text "0.40mil" at 8795.77,7043 h60
  text "3.5" at 9445.6,7043 h60
  text "1" at 6596.34,6923 h60
  text "TOP" at 7006.26,6923 h60
  text "1.40mil" at 8795.77,6923 h60
  text "Dielectric 1" at 7006.26,6803 h60
  text "FR-4" at 7936,6803 h60
  text "4.00mil" at 8795.77,6803 h60
  text "4.3" at 9445.6,6803 h60
  text "2" at 6596.34,6683 h60
  text "GND1" at 7006.26,6683 h60
  text "0.70mil" at 8795.77,6683 h60
  text "Dielectric2" at 7006.26,6563 h60
  text "FR-4" at 7936,6563 h60
  text "6.00mil" at 8795.77,6563 h60
  text "4.3" at 9445.6,6563 h60
  text "3" at 6596.34,6443 h60
  text "POWER1" at 7006.26,6443 h60
  text "0.70mil" at 8795.77,6443 h60
  text "Dielectric3" at 7006.26,6323 h60
  text "FR-4" at 7936,6323 h60
  text "35.60mil" at 8795.77,6323 h60
  text "4.5" at 9445.6,6323 h60
  text "4" at 6596.34,6203 h60
  text "INNER1" at 7006.26,6203 h60
  text "0.70mil" at 8795.77,6203 h60
  text "Dielectric4" at 7006.26,6083 h60
  text "FR-4" at 7936,6083 h60
  text "6.00mil" at 8795.77,6083 h60
  text "4.3" at 9445.6,6083 h60
  text "5" at 6596.34,5963 h60
  text "GND2" at 7006.26,5963 h60
  text "0.70mil" at 8795.77,5963 h60
  text "Dielectric5" at 7006.26,5843 h60
  text "FR-4" at 7936,5843 h60
  text "4.00mil" at 8795.77,5843 h60
  text "4.3" at 9445.6,5843 h60
  text "6" at 6596.34,5723 h60
  text "BOTTOM" at 7006.26,5723 h60
  text "1.40mil" at 8795.77,5723 h60
  text "Bottom Solder" at 7006.26,5603 h60
  text "Solder Resist" at 7936,5603 h60
  text "0.40mil" at 8795.77,5603 h60
  text "3.5" at 9445.6,5603 h60
  text "Bottom Overlay" at 7006.26,5483 h60
  text ".Layer_Name" at 577,-858.49 h60
M13 Component Bodies Top:
  text ".Layer_Name" at 577,-858.49 h60
M14 Component Bodies Bottom:
  text ".Layer_Name" at 577,-858.49 h60
M15 Courtyards Top:
  text ".Layer_Name" at 577,-858.49 h60
M16 Courtyards Bottom:
  text ".Layer_Name" at 577,-858.49 h60
Drill Drawing:
  circle w10: c5363.72,3179.64 r27.63
  lines w10: 5336.09,3276.34 5391.34,3276.34 5391.34,3331.59 5336.09,3331.59 5336.09,3276.34 ; 5336.09,3455.91 5391.34,3455.91 5363.72,3400.66 5336.09,3455.91
  lines w12: 5286,3114.72 8318.56,3114.72 ; 5286,3487.68 8318.56,3487.68 ; 5623.86,2990.4 5623.86,3612 ; 5955.86,2990.4 5955.86,3612 ; 6592.43,2990.4 6592.43,3612 ; 6851.57,2990.4 6851.57,3612 ; 7226.72,2990.4 7226.72,3612 ; 7752.13,2990.4 7752.13,3612 ; 5286,2990.4 8318.56,2990.4 8318.56,3612 5286,3612 5286,2990.4
  text "Symbol" at 5360.59,3524.98 h72
  text "Quantity" at 5661.16,3524.98 h72
  text "Finished Hole Size" at 5993.16,3524.98 h72
  text "Plated" at 6629.72,3524.98 h72
  text "Hole Type" at 6888.86,3524.98 h72
  text "Drill Layer Pair" at 7264.02,3524.98 h72
  text "Hole Tolerance" at 7789.43,3524.98 h72
  text "154" at 5661.16,3400.66 h60
  text "6.00mil (0.152mm)" at 5993.16,3400.66 h60
  text "PTH" at 6629.72,3400.66 h60
  text "Round" at 6888.86,3400.66 h60
  text "TOP - BOTTOM" at 7264.02,3400.66 h60
  text "11" at 5661.16,3276.34 h60
  text "17.72mil (0.450mm)" at 5993.16,3276.34 h60
  text "PTH" at 6629.72,3276.34 h60
  text "Round" at 6888.86,3276.34 h60
  text "TOP - BOTTOM" at 7264.02,3276.34 h60
  text "3" at 5661.16,3152.02 h60
  text "66.93mil (1.700mm)" at 5993.16,3152.02 h60
  text "PTH" at 6629.72,3152.02 h60
  text "Round" at 6888.86,3152.02 h60
  text "TOP - BOTTOM" at 7264.02,3152.02 h60
  text "168 Total" at 5661.16,3027.7 h60
  text ".Layer_Name" at 577,-858.49 h60
Mechanical 17:
  text ".Layer_Name" at 577,-858.49 h60
Mechanical 18:
  text ".Layer_Name" at 577,-858.49 h60
Mechanical 19:
  text ".Layer_Name" at 577,-858.49 h60

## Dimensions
0,-400 to 1000,-400 on M2 Board Dimensions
